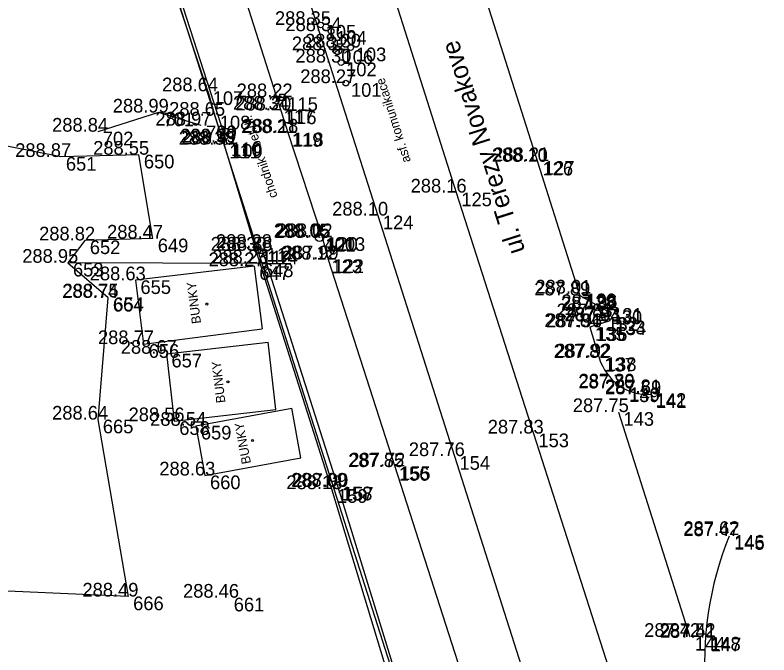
# Model space of a CAD drawing. Extents: x -599970 to -599524, y -1154772 to -1154457.
# Drawn here: x -599677.05 to -599644, y -1154635.29 to -1154607.23 of the extents above; entities that cross this region are included whole.
import ezdxf

# ---------------------------------------------------------------- set-up
doc = ezdxf.new("R2010")
doc.units = 0
for name, color, linetype in [('Z-BUDOVY', 7, 'Continuous'), ('Z-KANALIZACNI SACHTY VPUSTI', 7, 'Continuous'), ('Z-KATASTRALNI MAPA', 7, 'Continuous'), ('Z-NAZVY ULIC A REK', 7, 'Continuous'), ('Z-PEVNE BODY-CISLO', 7, 'Continuous'), ('Z-PEVNE BODY-VYSKA', 7, 'Continuous'), ('Z-PEVNE BODY-ZNACKA', 7, 'Continuous'), ('Z-PLOT DRATENY', 7, 'Continuous'), ('Z-PODROBNE BODY', 7, 'Continuous'), ('Z-PODROBNE BODY-CISLO', 7, 'Continuous'), ('Z-PODROBNE BODY-VYSKA', 7, 'Continuous'), ('Z-POPISY OBJEKTU A ZPEVNENYCH PLOCH', 7, 'Continuous'), ('Z-SCHODY', 7, 'Continuous'), ('Z-TERENNI HRANY PATY', 7, 'Continuous'), ('Z-VODOROVNE ZNACENI', 7, 'Continuous'), ('Z-VODOVODNI SACHTY SOUPATA HYDRANTY', 7, 'Continuous'), ('Z-VSTUPY VJEZDY', 7, 'Continuous'), ('Z-ZPEVNENE PLOCHY', 7, 'Continuous')]:
    doc.layers.add(name, color=color, linetype=linetype)

msp = doc.modelspace()

# ---------------------------------------------------------------- linework, layer by layer
at = {"layer": 'Z-BUDOVY'}
for p, q in [((-599666.57, -1154618.24), (-599666.22, -1154620.99)), ((-599671.42, -1154621.66), (-599666.22, -1154620.99)), ((-599670.42, -1154622.08), (-599665.96, -1154621.57)), ((-599669.13, -1154625.24), (-599664.92, -1154624.47))]:
    msp.add_line(p, q, dxfattribs=at)
for points in [[(-599666.57, -1154618.24), (-599671.78, -1154618.86), (-599671.42, -1154621.66)], [(-599670.08, -1154625.04), (-599665.62, -1154624.53), (-599665.96, -1154621.57)], [(-599670.42, -1154622.08), (-599670.08, -1154625.04)], [(-599668.73, -1154627.42), (-599664.52, -1154626.65), (-599664.92, -1154624.47)], [(-599669.13, -1154625.24), (-599668.73, -1154627.42)]]:
    msp.add_lwpolyline(points, dxfattribs=at)
at = {"layer": 'Z-KANALIZACNI SACHTY VPUSTI'}
for p, q in [((-599665.465, -1154610.83), (-599665.215, -1154610.83)), ((-599651.435, -1154620.48), (-599651.185, -1154620.48))]:
    msp.add_line(p, q, dxfattribs=at)
for points in [[(-599665.465, -1154610.955), (-599665.215, -1154610.955), (-599665.215, -1154610.705), (-599665.465, -1154610.705)], [(-599651.435, -1154620.605), (-599651.185, -1154620.605), (-599651.185, -1154620.355), (-599651.435, -1154620.355)]]:
    msp.add_lwpolyline(points, close=True, dxfattribs=at)
at = {"layer": 'Z-KATASTRALNI MAPA'}
msp.add_line((-599658.96, -1154640.84), (-599673.37, -1154595.74), dxfattribs=at)
at = {"layer": 'Z-PEVNE BODY-ZNACKA'}
for radius in [0.188, 0.188, 0.00896, 0.00896]:
    msp.add_circle((-599663.71, -1154616.97), radius, dxfattribs=at)
at = {"layer": 'Z-PLOT DRATENY'}
for points in [[(-599668.61, -1154610.57), (-599670.08, -1154606.1), (-599673.51, -1154595.77)], [(-599668.3, -1154611.64), (-599667.88, -1154612.91)], [(-599662.86, -1154641.92), (-599659.31, -1154640.76), (-599663.16, -1154628.02), (-599666.48, -1154617.56)], [(-599666.41, -1154618.12), (-599674.74, -1154618.09)]]:
    msp.add_lwpolyline(points, dxfattribs=at)
at = {"layer": 'Z-PODROBNE BODY'}
for p, q in [((-599663.66, -1154607.66), (-599663.66, -1154607.66)), ((-599663.2, -1154607.93), (-599663.2, -1154607.93)), ((-599662.92, -1154608.77), (-599662.92, -1154608.77)), ((-599662.34, -1154608.65), (-599662.34, -1154608.65)), ((-599662.76, -1154609.31), (-599662.76, -1154609.31)), ((-599662.55, -1154610.21), (-599662.55, -1154610.21)), ((-599668.61, -1154610.57), (-599668.61, -1154610.57)), ((-599665.34, -1154610.83), (-599665.34, -1154610.83)), ((-599665.5, -1154611.38), (-599665.5, -1154611.38)), ((-599665.4, -1154611.41), (-599665.4, -1154611.41)), ((-599670.77, -1154611.5), (-599670.77, -1154611.5)), ((-599668.3, -1154611.64), (-599668.3, -1154611.64)), ((-599668.9, -1154612.07), (-599668.9, -1154612.07)), ((-599673.43, -1154612.34), (-599673.43, -1154612.34)), ((-599665.14, -1154612.4), (-599665.14, -1154612.4)), ((-599665.09, -1154612.38), (-599665.09, -1154612.38)), ((-599667.88, -1154612.91), (-599667.88, -1154612.91)), ((-599667.81, -1154612.81), (-599667.81, -1154612.81)), ((-599667.76, -1154612.89), (-599667.76, -1154612.89)), ((-599671.63, -1154613.35), (-599671.63, -1154613.35)), ((-599675.05, -1154613.45), (-599675.05, -1154613.45)), ((-599654.15, -1154613.66), (-599654.15, -1154613.66)), ((-599654.09, -1154613.63), (-599654.09, -1154613.63)), ((-599657.71, -1154615.01), (-599657.71, -1154615.01)), ((-599661.15, -1154616.02), (-599661.15, -1154616.02)), ((-599671.02, -1154617.03), (-599671.02, -1154617.03)), ((-599663.68, -1154617), (-599663.68, -1154617)), ((-599663.59, -1154616.97), (-599663.59, -1154616.97)), ((-599674, -1154617.11), (-599674, -1154617.11)), ((-599666.48, -1154617.56), (-599666.48, -1154617.56)), ((-599666.25, -1154617.44), (-599666.25, -1154617.44)), ((-599666.22, -1154617.56), (-599666.22, -1154617.56)), ((-599663.4, -1154617.95), (-599663.4, -1154617.95)), ((-599663.32, -1154617.94), (-599663.32, -1154617.94)), ((-599674.74, -1154618.09), (-599674.74, -1154618.09)), ((-599666.57, -1154618.24), (-599666.57, -1154618.24)), ((-599666.41, -1154618.12), (-599666.41, -1154618.12)), ((-599671.78, -1154618.86), (-599671.78, -1154618.86)), ((-599672.99, -1154619.63), (-599672.99, -1154619.63)), ((-599672.97, -1154619.61), (-599672.97, -1154619.61)), ((-599652.29, -1154619.52), (-599652.29, -1154619.52)), ((-599652.24, -1154619.44), (-599652.24, -1154619.44)), ((-599651.12, -1154620.18), (-599651.12, -1154620.18)), ((-599651.1, -1154620.08), (-599651.1, -1154620.08)), ((-599651.31, -1154620.48), (-599651.31, -1154620.48)), ((-599650.97, -1154620.63), (-599650.97, -1154620.63)), ((-599650.95, -1154620.66), (-599650.95, -1154620.66)), ((-599651.85, -1154620.91), (-599651.85, -1154620.91)), ((-599651.77, -1154620.92), (-599651.77, -1154620.92)), ((-599671.42, -1154621.66), (-599671.42, -1154621.66)), ((-599670.42, -1154622.08), (-599670.42, -1154622.08)), ((-599651.44, -1154622.26), (-599651.44, -1154622.26)), ((-599651.37, -1154622.24), (-599651.37, -1154622.24)), ((-599650.36, -1154623.6), (-599650.36, -1154623.6)), ((-599650.34, -1154623.56), (-599650.34, -1154623.56)), ((-599649.19, -1154623.81), (-599649.19, -1154623.81)), ((-599649.18, -1154623.86), (-599649.18, -1154623.86)), ((-599650.6, -1154624.64), (-599650.6, -1154624.64)), ((-599673.43, -1154624.97), (-599673.43, -1154624.97)), ((-599670.08, -1154625.04), (-599670.08, -1154625.04)), ((-599669.13, -1154625.24), (-599669.13, -1154625.24)), ((-599654.33, -1154625.58), (-599654.33, -1154625.58)), ((-599657.79, -1154626.57), (-599657.79, -1154626.57)), ((-599660.45, -1154627.05), (-599660.45, -1154627.05)), ((-599660.4, -1154627.02), (-599660.4, -1154627.02)), ((-599668.73, -1154627.42), (-599668.73, -1154627.42)), ((-599662.95, -1154627.91), (-599662.95, -1154627.91)), ((-599662.9, -1154627.92), (-599662.9, -1154627.92)), ((-599663.16, -1154628.02), (-599663.16, -1154628.02)), ((-599645.75, -1154630.03), (-599645.75, -1154630.03)), ((-599645.75, -1154630.08), (-599645.75, -1154630.08)), ((-599672.1, -1154632.73), (-599672.1, -1154632.73)), ((-599667.69, -1154632.78), (-599667.69, -1154632.78)), ((-599647.47, -1154634.5), (-599647.47, -1154634.5)), ((-599646.8, -1154634.5), (-599646.8, -1154634.5)), ((-599646.78, -1154634.54), (-599646.78, -1154634.54))]:
    msp.add_line(p, q, dxfattribs=at)
at = {"layer": 'Z-SCHODY'}
for centre in [(-599668.65, -1154619.9), (-599667.72, -1154623.31), (-599666.64, -1154625.88)]:
    msp.add_circle(centre, 0.0438, dxfattribs=at)
at = {"layer": 'Z-TERENNI HRANY PATY'}
msp.add_lwpolyline([(-599668.9, -1154612.07), (-599670.77, -1154611.5), (-599673.43, -1154612.34)], dxfattribs=at)
at = {"layer": 'Z-VODOROVNE ZNACENI'}
for points in [[(-599694.02, -1154499.99), (-599689.54, -1154514.32), (-599685.46, -1154527.42), (-599683.24, -1154534.53), (-599677.91, -1154551.43), (-599673.26, -1154566.04), (-599670.15, -1154575.91), (-599664.69, -1154593.08), (-599661.63, -1154602.65), (-599657.71, -1154615.01), (-599654.33, -1154625.58), (-599650.3, -1154638.13), (-599646.03, -1154651.51), (-599641.58, -1154665.41), (-599629.85, -1154702.06), (-599625.38, -1154716.06)], [(-599697.63, -1154501.15), (-599693.46, -1154514.34), (-599689.12, -1154528.02), (-599685.9, -1154538.22), (-599681.17, -1154553.13), (-599676.65, -1154567.39), (-599673.59, -1154577), (-599671.31, -1154584.14), (-599668.11, -1154594.2), (-599666.34, -1154599.75), (-599661.15, -1154616.02), (-599657.79, -1154626.57), (-599653.82, -1154639.02), (-599649.52, -1154652.61), (-599645.03, -1154666.6), (-599639.28, -1154684.62), (-599637.35, -1154690.63), (-599633.4, -1154703.39)], [(-599650.6, -1154624.64), (-599647.47, -1154634.5)]]:
    msp.add_lwpolyline(points, dxfattribs=at)
at = {"layer": 'Z-VODOVODNI SACHTY SOUPATA HYDRANTY'}
for p, q in [((-599663.045, -1154608.332), (-599662.795, -1154608.332)), ((-599662.92, -1154608.582), (-599662.92, -1154608.332)), ((-599663.067, -1154608.886), (-599662.772, -1154608.654))]:
    msp.add_line(p, q, dxfattribs=at)
for centre, radius in [((-599663.66, -1154607.66), 0.125), ((-599663.2, -1154607.93), 0.125), ((-599662.92, -1154608.77), 0.188), ((-599662.34, -1154608.65), 0.125), ((-599662.76, -1154609.31), 0.125), ((-599662.55, -1154610.21), 0.125)]:
    msp.add_circle(centre, radius, dxfattribs=at)
at = {"layer": 'Z-VSTUPY VJEZDY'}
for points in [[(-599668.61, -1154610.57), (-599668.3, -1154611.64)], [(-599667.88, -1154612.91), (-599666.48, -1154617.56)]]:
    msp.add_lwpolyline(points, dxfattribs=at)
at = {"layer": 'Z-ZPEVNENE PLOCHY'}
for points in [[(-599687.9, -1154498.79), (-599683.81, -1154511.87), (-599681.17, -1154520.27), (-599680.7, -1154530), (-599680.59, -1154530.5), (-599678.7, -1154536.46), (-599674.09, -1154550.98), (-599669.64, -1154565.06), (-599666.53, -1154574.78), (-599664.2, -1154582.16), (-599662.32, -1154587.97), (-599661.17, -1154588.61), (-599661.03, -1154589.1), (-599661.9, -1154589.37), (-599661.11, -1154591.93), (-599657.79, -1154602.2), (-599654.15, -1154613.66), (-599652.29, -1154619.52), (-599651.12, -1154620.18), (-599650.97, -1154620.63), (-599651.85, -1154620.91), (-599651.44, -1154622.26)], [(-599672.4, -1154589.48), (-599670.73, -1154594.81), (-599667.36, -1154605.26), (-599665.4, -1154611.41), (-599665.09, -1154612.38), (-599663.59, -1154616.97), (-599663.32, -1154617.94), (-599660.4, -1154627.02), (-599656.6, -1154638.85), (-599656.29, -1154639.8), (-599655.25, -1154643.15), (-599654.93, -1154644.12), (-599651.93, -1154653.5), (-599647.41, -1154667.76), (-599641.59, -1154686.01), (-599637.45, -1154690.75), (-599637.27, -1154691.05), (-599637.22, -1154691.51), (-599636.57, -1154701.7), (-599631.18, -1154718.34)], [(-599673.31, -1154595.75), (-599669.97, -1154605.99), (-599667.76, -1154612.89), (-599667.88, -1154612.91)], [(-599671.02, -1154617.03), (-599671.63, -1154613.35), (-599675.05, -1154613.45), (-599680.32, -1154612.41), (-599686.62, -1154610.91), (-599694.45, -1154609.33), (-599700.34, -1154608.57), (-599705.79, -1154608.71), (-599715.78, -1154610.69), (-599725.58, -1154612.61), (-599730.02, -1154613.49), (-599735.64, -1154614.56), (-599743.95, -1154616.26), (-599754.96, -1154619.25), (-599762.63, -1154622.27), (-599761.65, -1154625.43)], [(-599671.02, -1154617.03), (-599674, -1154617.11), (-599674.74, -1154618.09), (-599672.97, -1154619.61), (-599672.99, -1154619.63), (-599673.43, -1154624.97), (-599672.1, -1154632.73), (-599679.37, -1154632.4), (-599679.21, -1154625.35), (-599679.14, -1154619.7), (-599679.61, -1154616.32), (-599687.06, -1154613.66), (-599695, -1154612.23), (-599700.47, -1154611.47), (-599705.51, -1154611.86), (-599715.16, -1154613.61), (-599724.96, -1154615.5), (-599735.23, -1154617.18), (-599743.14, -1154619.2), (-599754.14, -1154621.91)], [(-599666.48, -1154617.56), (-599666.25, -1154617.44), (-599662.9, -1154627.92), (-599658.99, -1154640.64)]]:
    msp.add_lwpolyline(points, dxfattribs=at)
for centre, radius, start, end in [((-599649.312, -1154621.65), 2.214, 195.9966, 273.4091), ((-599631.948, -1154635.616), 14.871, 158.143, 185.1059)]:
    msp.add_arc(centre, radius, start, end, dxfattribs=at)

# ---------------------------------------------------------------- texts
at = {"layer": 'Z-NAZVY ULIC A REK'}
msp.add_text('ul. Terezy Novakove', height=0.8, rotation=107.6212, dxfattribs=at).set_placement((-599654.68, -1154617.56))
at = {"layer": 'Z-PEVNE BODY-CISLO'}
msp.add_text(' 4003', height=0.6, dxfattribs=at).set_placement((-599663.71, -1154617.57))
at = {"layer": 'Z-PEVNE BODY-VYSKA'}
msp.add_text('288.05 ', height=0.6, dxfattribs=at).set_placement((-599665.71, -1154616.97))
at = {"layer": 'Z-PODROBNE BODY-CISLO'}
for s, p in [(' 105', (-599663.66, -1154608.26)), (' 104', (-599663.2, -1154608.53)), (' 106', (-599662.92, -1154609.37)), (' 103', (-599662.34, -1154609.25)), (' 102', (-599662.76, -1154609.91)), (' 101', (-599662.55, -1154610.81)), (' 107', (-599668.61, -1154611.17)), (' 115', (-599665.34, -1154611.43)), (' 117', (-599665.5, -1154611.98)), (' 116', (-599665.4, -1154612.01)), (' 701', (-599670.77, -1154612.1)), (' 108', (-599668.3, -1154612.24)), (' 700', (-599668.9, -1154612.67)), (' 702', (-599673.43, -1154612.94)), (' 119', (-599665.14, -1154613)), (' 118', (-599665.09, -1154612.98)), (' 111', (-599667.88, -1154613.51)), (' 110', (-599667.81, -1154613.41)), (' 109', (-599667.76, -1154613.49)), (' 651', (-599675.05, -1154614.05)), (' 650', (-599671.63, -1154613.95)), (' 126', (-599654.15, -1154614.26)), (' 127', (-599654.09, -1154614.23)), (' 125', (-599657.71, -1154615.61)), (' 124', (-599661.15, -1154616.62)), (' 649', (-599671.02, -1154617.63)), (' 121', (-599663.68, -1154617.6)), (' 120', (-599663.59, -1154617.57)), (' 652', (-599674, -1154617.71)), (' 112', (-599666.48, -1154618.16)), (' 113', (-599666.25, -1154618.04)), (' 114', (-599666.22, -1154618.16)), (' 123', (-599663.4, -1154618.55)), (' 122', (-599663.32, -1154618.54)), (' 653', (-599674.74, -1154618.69)), (' 647', (-599666.57, -1154618.84)), (' 648', (-599666.41, -1154618.72)), (' 655', (-599671.78, -1154619.46)), (' 664', (-599672.99, -1154620.23)), (' 654', (-599672.97, -1154620.21)), (' 128', (-599652.29, -1154620.12)), (' 129', (-599652.24, -1154620.04)), (' 130', (-599651.12, -1154620.78)), (' 131', (-599651.1, -1154620.68)), (' 132', (-599651.31, -1154621.08)), (' 133', (-599650.97, -1154621.23)), (' 134', (-599650.95, -1154621.26)), (' 135', (-599651.85, -1154621.51)), (' 136', (-599651.77, -1154621.52)), (' 656', (-599671.42, -1154622.26)), (' 657', (-599670.42, -1154622.68)), (' 137', (-599651.44, -1154622.86)), (' 138', (-599651.37, -1154622.84)), (' 139', (-599650.36, -1154624.2)), (' 140', (-599650.34, -1154624.16)), (' 142', (-599649.19, -1154624.41)), (' 141', (-599649.18, -1154624.46)), (' 143', (-599650.6, -1154625.24)), (' 665', (-599673.43, -1154625.57)), (' 658', (-599670.08, -1154625.64)), (' 659', (-599669.13, -1154625.84)), (' 153', (-599654.33, -1154626.18)), (' 154', (-599657.79, -1154627.17)), (' 156', (-599660.45, -1154627.65)), (' 155', (-599660.4, -1154627.62)), (' 660', (-599668.73, -1154628.02)), (' 158', (-599662.95, -1154628.51)), (' 157', (-599662.9, -1154628.52)), (' 159', (-599663.16, -1154628.62)), (' 146', (-599645.75, -1154630.63)), (' 145', (-599645.75, -1154630.68)), (' 666', (-599672.1, -1154633.33)), (' 661', (-599667.69, -1154633.38)), (' 144', (-599647.47, -1154635.1)), (' 148', (-599646.8, -1154635.1)), (' 147', (-599646.78, -1154635.14))]:
    msp.add_text(s, height=0.6, dxfattribs=at).set_placement(p)
at = {"layer": 'Z-PODROBNE BODY-VYSKA'}
for s, p in [('288.35 ', (-599665.66, -1154607.66)), ('288.34 ', (-599665.2, -1154607.93)), ('288.30 ', (-599664.34, -1154608.65)), ('288.32 ', (-599664.92, -1154608.77)), ('288.30 ', (-599664.76, -1154609.31)), ('288.27 ', (-599664.55, -1154610.21)), ('288.64 ', (-599670.61, -1154610.57)), ('288.22 ', (-599667.34, -1154610.83)), ('288.34 ', (-599667.5, -1154611.38)), ('288.99 ', (-599672.77, -1154611.5)), ('288.65 ', (-599670.3, -1154611.64)), ('288.20 ', (-599667.4, -1154611.41)), ('288.84 ', (-599675.43, -1154612.34)), ('288.97 ', (-599670.9, -1154612.07)), ('288.18 ', (-599667.09, -1154612.38)), ('288.21 ', (-599667.14, -1154612.4)), ('288.38 ', (-599669.88, -1154612.91)), ('288.59 ', (-599669.81, -1154612.81)), ('288.41 ', (-599669.76, -1154612.89)), ('288.55 ', (-599673.63, -1154613.35)), ('288.87 ', (-599677.05, -1154613.45)), ('288.10 ', (-599656.15, -1154613.66)), ('288.21 ', (-599656.09, -1154613.63)), ('288.16 ', (-599659.71, -1154615.01)), ('288.10 ', (-599663.15, -1154616.02)), ('288.05 ', (-599665.68, -1154617)), ('288.02 ', (-599665.59, -1154616.97)), ('288.82 ', (-599676, -1154617.11)), ('288.47 ', (-599673.02, -1154617.03)), ('288.30 ', (-599668.48, -1154617.56)), ('288.28 ', (-599668.25, -1154617.44)), ('288.38 ', (-599668.22, -1154617.56)), ('288.12 ', (-599665.4, -1154617.95)), ('287.99 ', (-599665.32, -1154617.94)), ('288.95 ', (-599676.74, -1154618.09)), ('288.27 ', (-599668.57, -1154618.24)), ('288.23 ', (-599668.41, -1154618.12)), ('288.63 ', (-599673.78, -1154618.86)), ('288.74 ', (-599674.99, -1154619.63)), ('288.75 ', (-599674.97, -1154619.61)), ('287.89 ', (-599654.29, -1154619.52)), ('288.01 ', (-599654.24, -1154619.44)), ('287.82 ', (-599653.12, -1154620.18)), ('287.96 ', (-599653.1, -1154620.08)), ('287.83 ', (-599653.31, -1154620.48)), ('287.83 ', (-599652.97, -1154620.63)), ('287.94 ', (-599652.95, -1154620.66)), ('287.84 ', (-599653.85, -1154620.91)), ('287.96 ', (-599653.77, -1154620.92)), ('288.77 ', (-599673.42, -1154621.66)), ('288.67 ', (-599672.42, -1154622.08)), ('287.82 ', (-599653.44, -1154622.26)), ('287.92 ', (-599653.37, -1154622.24)), ('287.76 ', (-599652.36, -1154623.6)), ('287.89 ', (-599652.34, -1154623.56)), ('287.81 ', (-599651.19, -1154623.81)), ('287.69 ', (-599651.18, -1154623.86)), ('287.75 ', (-599652.6, -1154624.64)), ('288.64 ', (-599675.43, -1154624.97)), ('288.56 ', (-599672.08, -1154625.04)), ('288.54 ', (-599671.13, -1154625.24)), ('287.83 ', (-599656.33, -1154625.58)), ('287.76 ', (-599659.79, -1154626.57)), ('287.85 ', (-599662.45, -1154627.05)), ('287.72 ', (-599662.4, -1154627.02)), ('288.63 ', (-599670.73, -1154627.42)), ('288.09 ', (-599664.95, -1154627.91)), ('287.90 ', (-599664.9, -1154627.92)), ('288.13 ', (-599665.16, -1154628.02)), ('287.62 ', (-599647.75, -1154630.03)), ('287.47 ', (-599647.75, -1154630.08)), ('288.49 ', (-599674.1, -1154632.73)), ('288.46 ', (-599669.69, -1154632.78)), ('287.42 ', (-599649.47, -1154634.5)), ('287.52 ', (-599648.8, -1154634.5)), ('287.41 ', (-599648.78, -1154634.54))]:
    msp.add_text(s, height=0.6, dxfattribs=at).set_placement(p)
at = {"layer": 'Z-POPISY OBJEKTU A ZPEVNENYCH PLOCH'}
for s, rotation, p in [('asf. komunikace', 107.6212, (-599659.7, -1154613.63)), ('chodnik - bet.dl.', 107.8271, (-599665.54, -1154615.18)), ('BUNKY', 97.3264, (-599668.9, -1154620.74)), ('BUNKY', 96.5526, (-599667.83, -1154624.22)), ('BUNKY', 100.3973, (-599666.71, -1154626.88))]:
    msp.add_text(s, height=0.4, rotation=rotation, dxfattribs=at).set_placement(p)

doc.saveas('drawing.dxf')
